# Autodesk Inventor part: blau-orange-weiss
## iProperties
Created: 2004-10
Part Number: blau-orange-weiss
Document SubType Name: Modeling
Designer: sahrens
Manufacturer: Standard
Standards Organization: Custom
Author: sahrens
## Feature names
1. Extrusion1
2. Rundung2 [Fillet]
